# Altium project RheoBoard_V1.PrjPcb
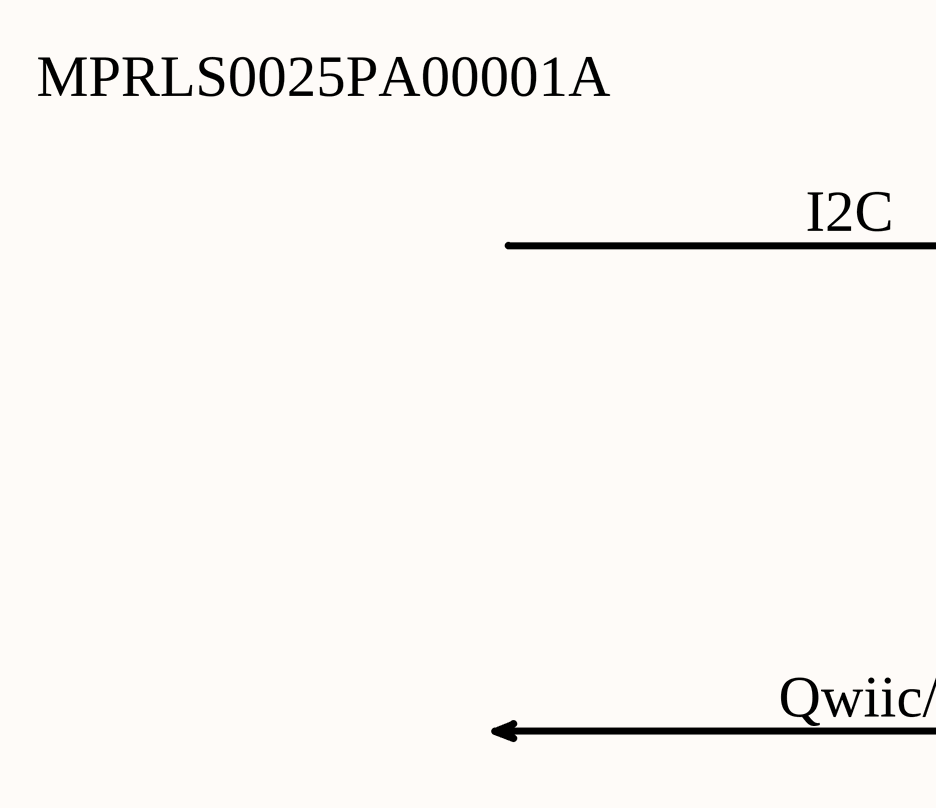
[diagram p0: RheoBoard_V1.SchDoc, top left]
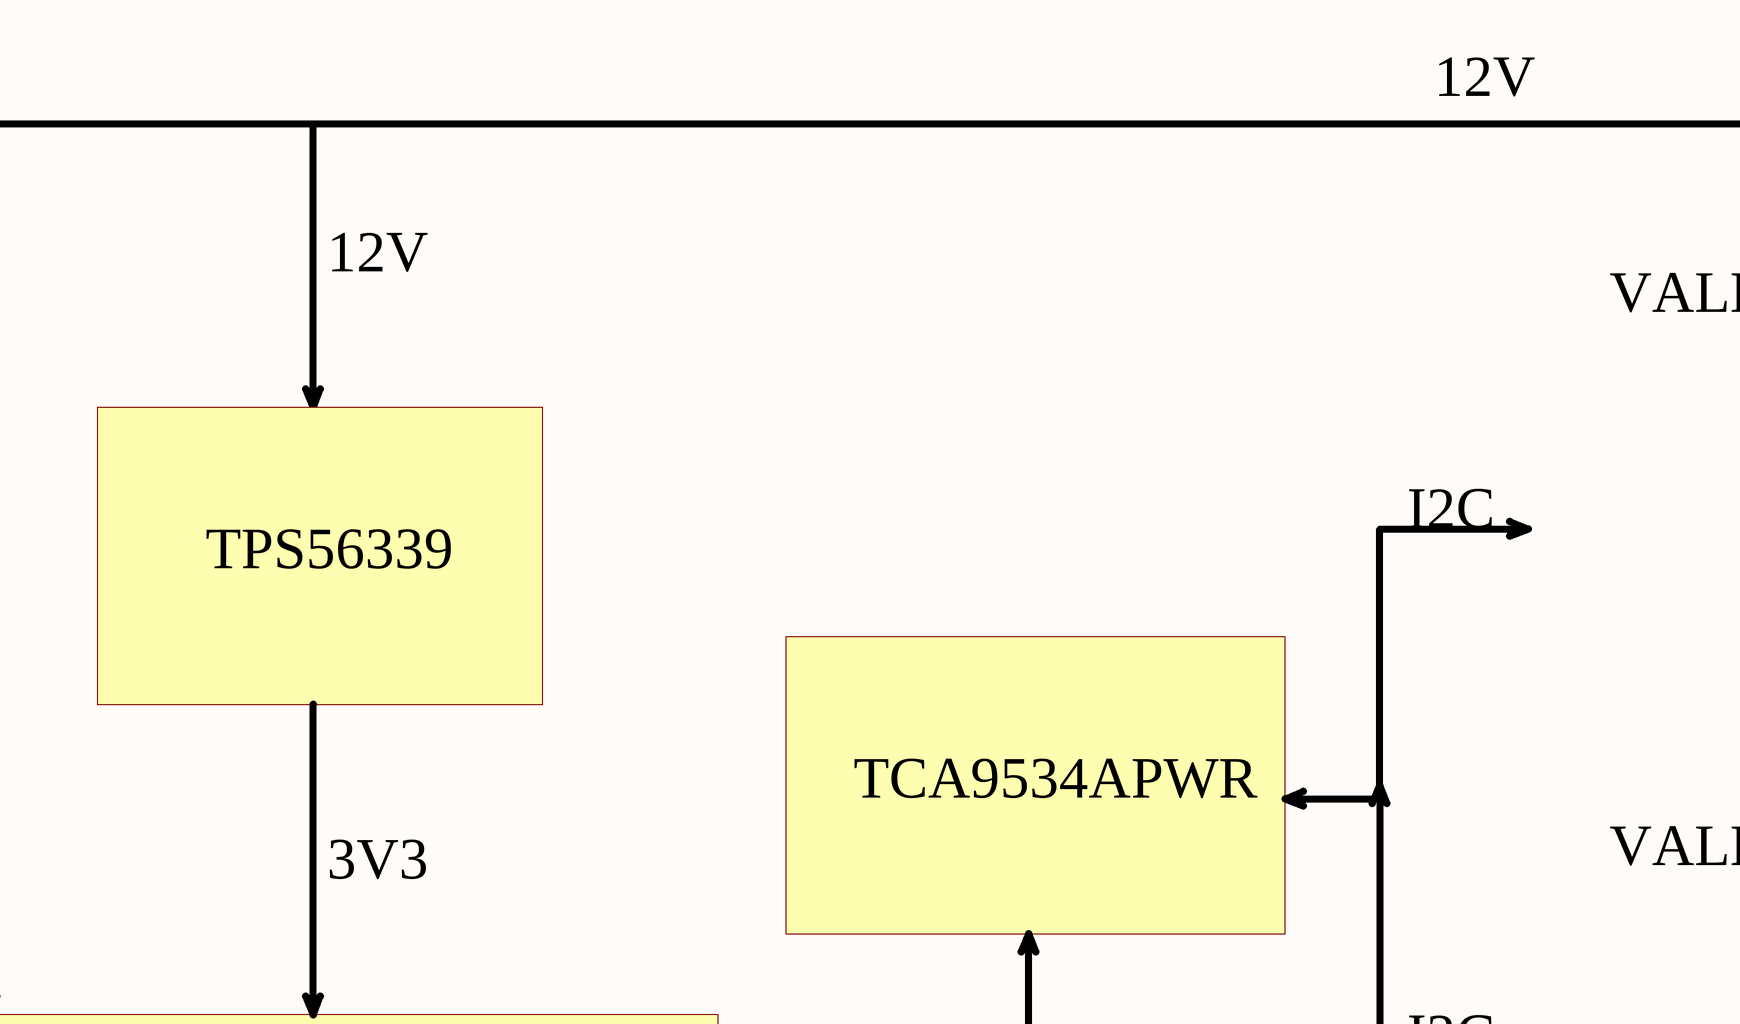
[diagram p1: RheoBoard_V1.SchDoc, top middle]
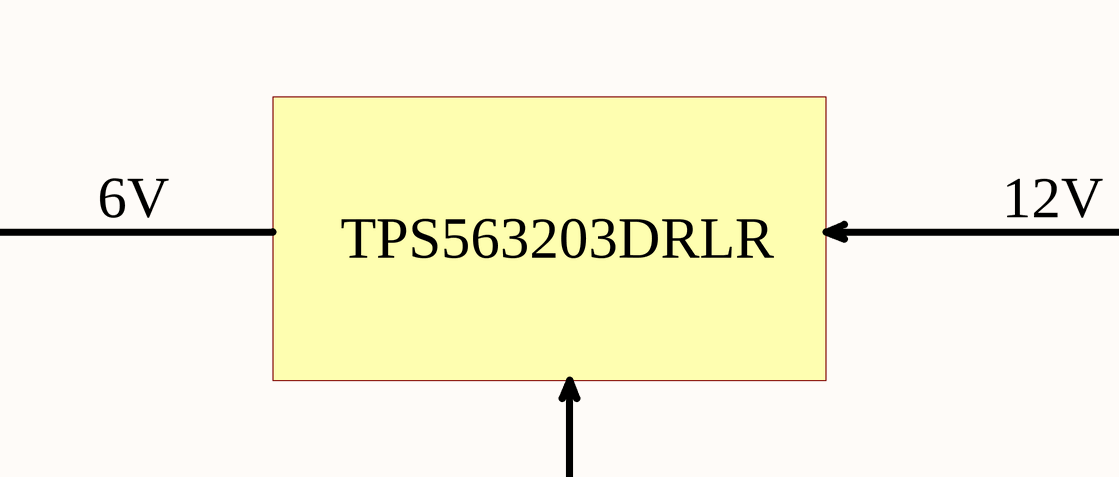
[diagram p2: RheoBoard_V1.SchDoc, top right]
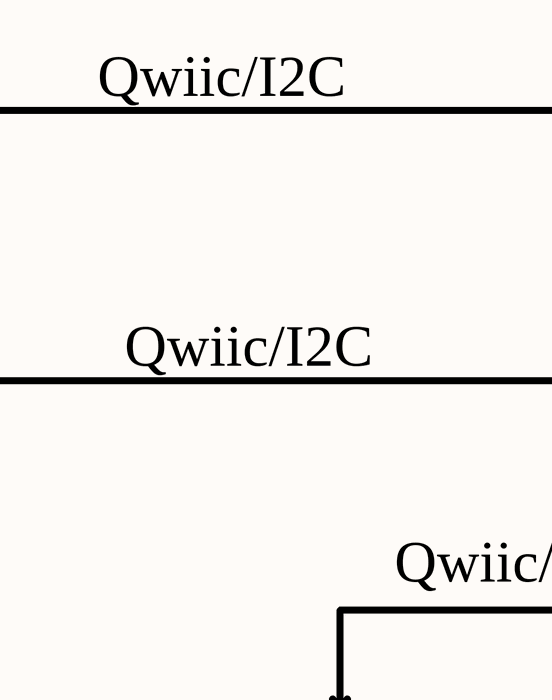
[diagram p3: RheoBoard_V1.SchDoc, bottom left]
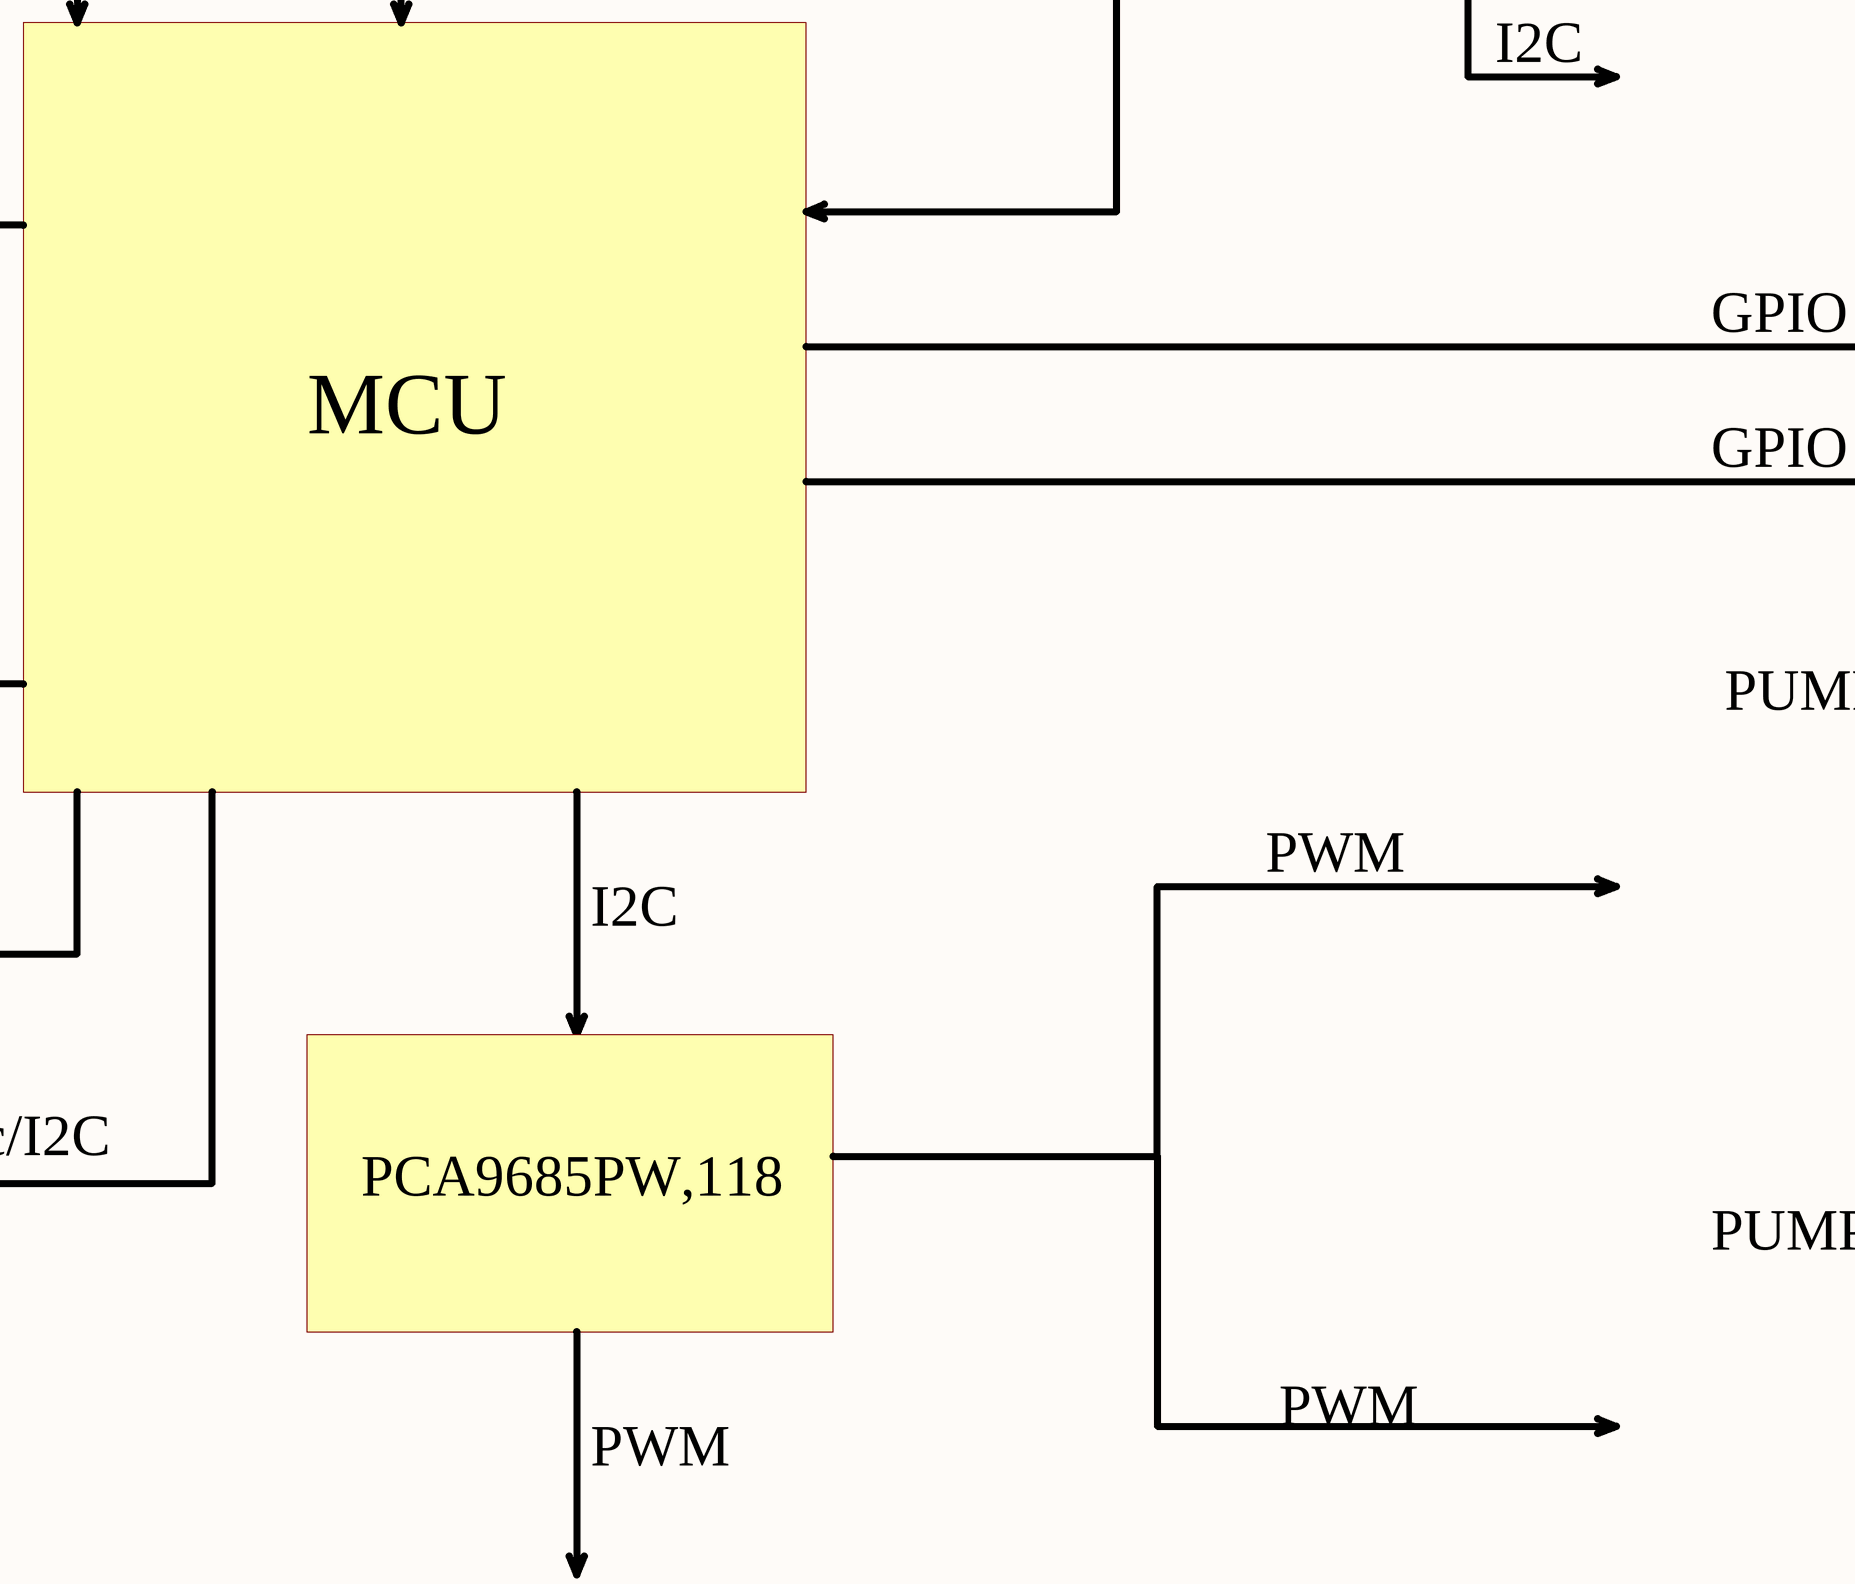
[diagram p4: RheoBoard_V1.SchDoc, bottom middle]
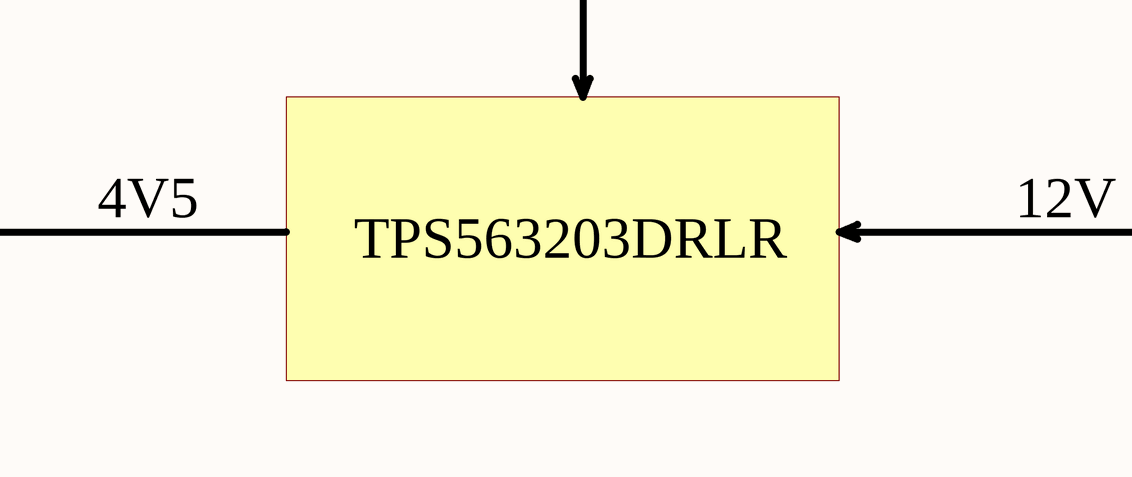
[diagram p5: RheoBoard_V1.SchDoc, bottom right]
3 sheets, 132 parts. Net scope: flat (ports and power ports of the same name join across sheets).
Board file: RheoBoard_V1.PcbDoc
Sheets:
  RheoBoard_V1.SchDoc
  MAIN.SchDoc
  POWER.SchDoc

## Sheet RheoBoard_V1.SchDoc
size A0; SheetNumber: 1; SheetTotal: 3

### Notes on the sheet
- 12V
- VALE1
- I2C
- MPRLS0025PA00001A
- TPS56339
- TCA9534APWR
- 6V
- 3V3
- VALE2
- TPS563203DRLR
- Qwiic/I2C
- GPIO
- MCU
- PUMP1
- PWM
- 4V5
- PCA9685PW,118
- PUMP2

## Sheet MAIN.SchDoc
size A1; SheetNumber: 2; SheetTotal: 3
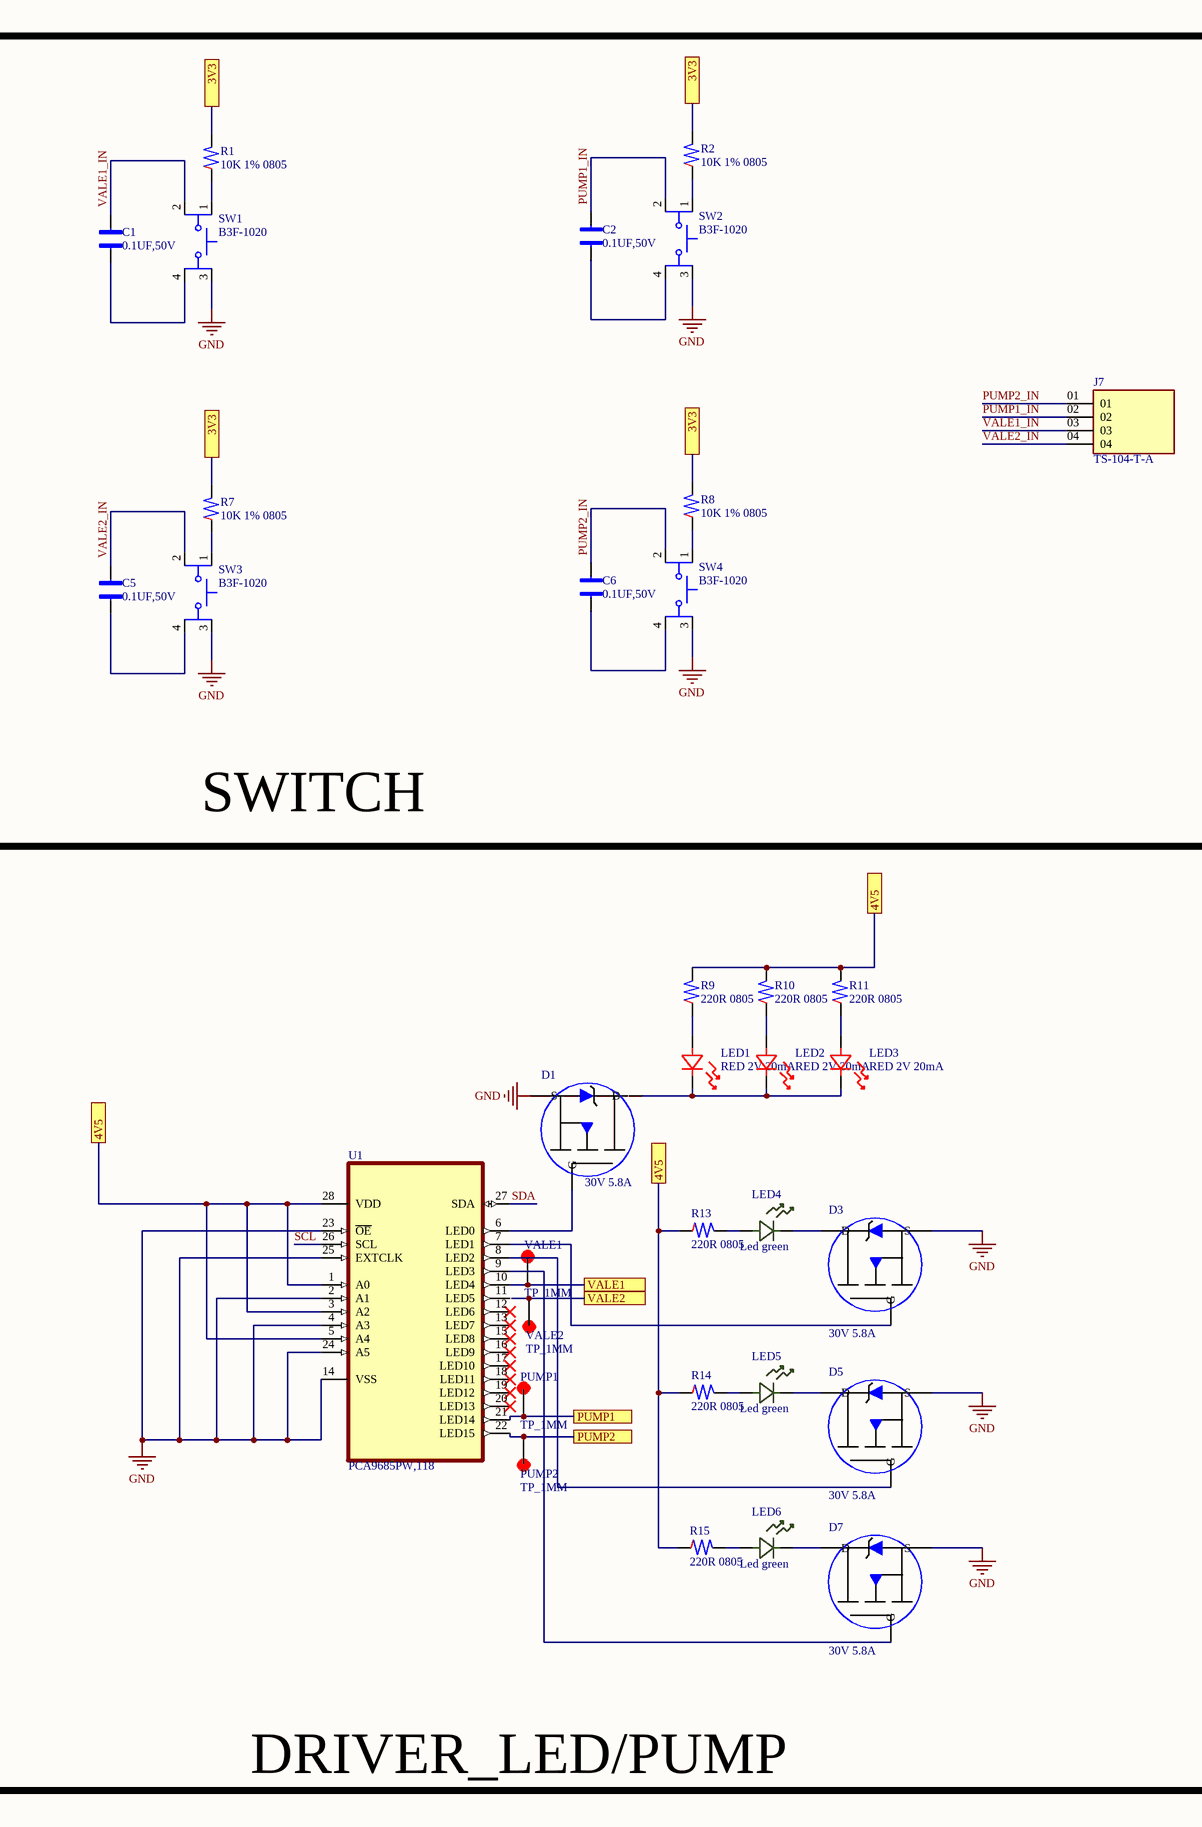
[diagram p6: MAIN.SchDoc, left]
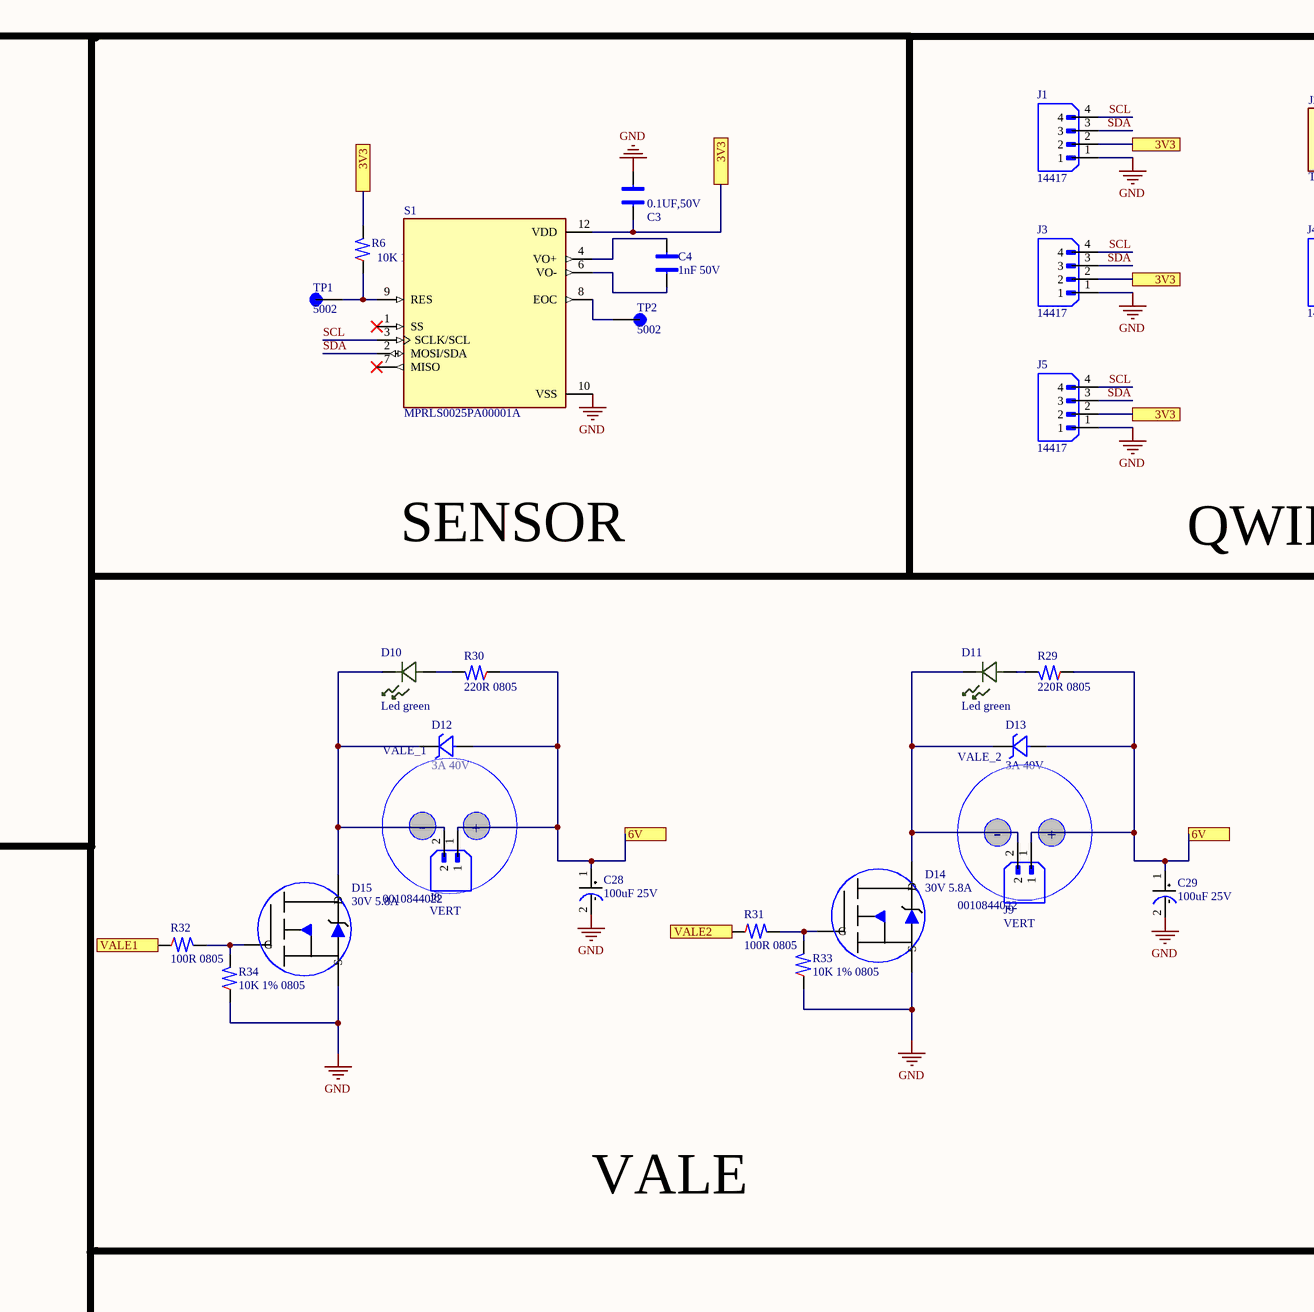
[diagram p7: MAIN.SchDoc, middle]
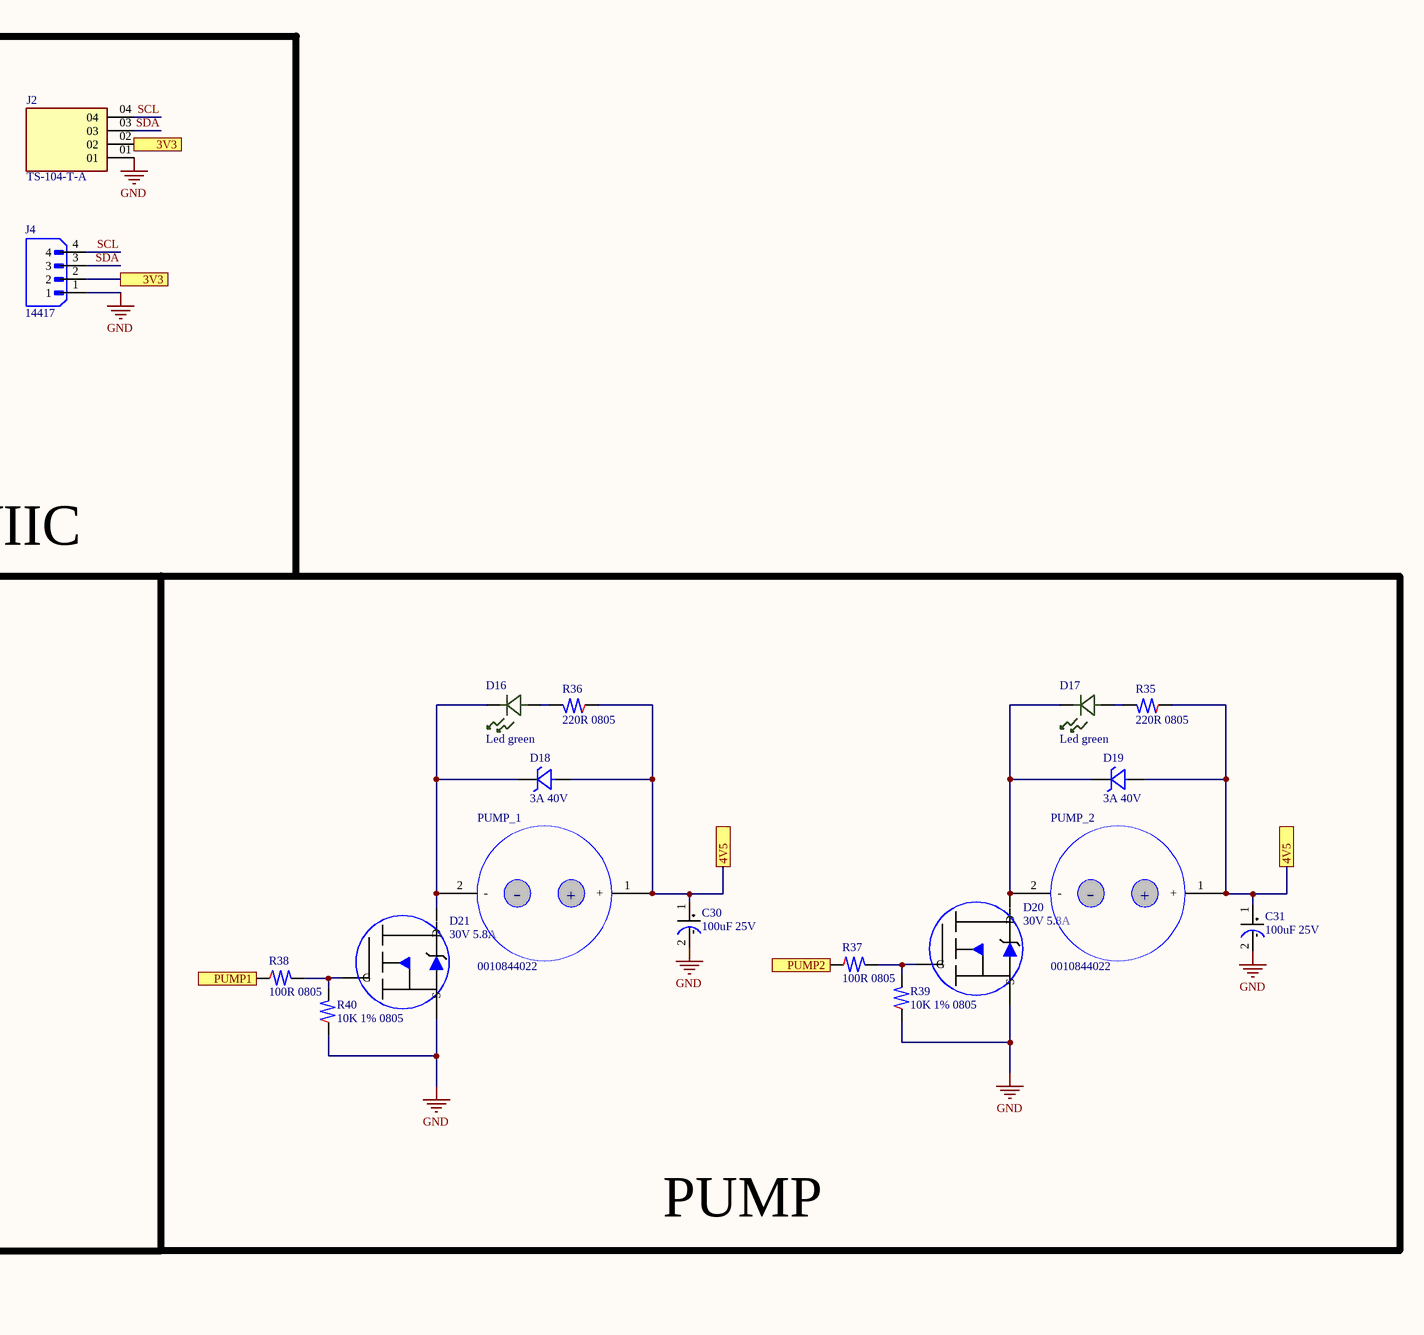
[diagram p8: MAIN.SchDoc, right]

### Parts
C1  0.1UF,50V  [CAP_CER_0805]
C2  0.1UF,50V  [CAP_CER_0805]
C3  0.1UF,50V  [CAP_CER_0805]
C4  1nF 50V  [CAP_CER_0805]
C5  0.1UF,50V  [CAP_CER_0805]
C6  0.1UF,50V  [CAP_CER_0805]
C28  100uF 25V  [CAP_ALUM_SMD_D10_H12.4]
C29  100uF 25V  [CAP_ALUM_SMD_D10_H12.4]
C30  100uF 25V  [CAP_ALUM_SMD_D10_H12.4]
C31  100uF 25V  [CAP_ALUM_SMD_D10_H12.4]
D1  30V 5.8A  [SOT-23-3]
D3  30V 5.8A  [SOT-23-3]
D5  30V 5.8A  [SOT-23-3]
D7  30V 5.8A  [SOT-23-3]
D10  Led green  [LED_LS R976_AOS]
D11  Led green  [LED_LS R976_AOS]
D12  3A 40V  [DO214AA]
D13  3A 40V  [DO214AA]
D14  30V 5.8A  [SOT-23-3]
D15  30V 5.8A  [SOT-23-3]
D16  Led green  [LED_LS R976_AOS]
D17  Led green  [LED_LS R976_AOS]
D18  3A 40V  [DO214AA]
D19  3A 40V  [DO214AA]
D20  30V 5.8A  [SOT-23-3]
D21  30V 5.8A  [SOT-23-3]
J1  14417  [SPARKFUN_PRT-14417]
J2  TS-104-T-A  [HDR_THT_1x04_P2.54]
J3  14417  [SPARKFUN_PRT-14417]
J4  14417  [SPARKFUN_PRT-14417]
J5  14417  [SPARKFUN_PRT-14417]
J7  TS-104-T-A  [HDR_THT_1x04_P2.54]
J8  VERT  [CONN_SMD_TOP_P2.50]
J9  VERT  [CONN_SMD_TOP_P2.50]
LED1  RED 2V 20mA  [LED_LS R976_AOS]
LED2  RED 2V 20mA  [LED_LS R976_AOS]
LED3  RED 2V 20mA  [LED_LS R976_AOS]
LED4  Led green  [LED_LS R976_AOS]
LED5  Led green  [LED_LS R976_AOS]
LED6  Led green  [LED_LS R976_AOS]
PUMP1  TP_1MM  [TP_1mm]
PUMP2  TP_1MM  [TP_1mm]
PUMP_1  0010844022  [PUMP_LPM - ZR370-02PM]
PUMP_2  0010844022  [PUMP_LPM - ZR370-02PM]
R1  10K 1% 0805  [RES_0805]
R2  10K 1% 0805  [RES_0805]
R6  10K 1% 0805  [RES_0805]
R7  10K 1% 0805  [RES_0805]
R8  10K 1% 0805  [RES_0805]
R9  220R 0805  [RES_0805]
R10  220R 0805  [RES_0805]
R11  220R 0805  [RES_0805]
R13  220R 0805  [RES_0805]
R14  220R 0805  [RES_0805]
R15  220R 0805  [RES_0805]
R29  220R 0805  [RES_0805]
R30  220R 0805  [RES_0805]
R31  100R 0805  [RES_0805]
R32  100R 0805  [RES_0805]
R33  10K 1% 0805  [RES_0805]
R34  10K 1% 0805  [RES_0805]
R35  220R 0805  [RES_0805]
R36  220R 0805  [RES_0805]
R37  100R 0805  [RES_0805]
R38  100R 0805  [RES_0805]
R39  10K 1% 0805  [RES_0805]
R40  10K 1% 0805  [RES_0805]
S1  MPRLS0025PA00001A  [XDCR_MPRLS0025PA00001A]
SW1  B3F-1020  [SW_B3F-1000_OMR]
SW2  B3F-1020  [SW_B3F-1000_OMR]
SW3  B3F-1020  [SW_B3F-1000_OMR]
SW4  B3F-1020  [SW_B3F-1000_OMR]
TP1  5002  [KEYSTONE_5002]
TP2  5002  [KEYSTONE_5002]
U1  PCA9685PW,118  [TSSOP-28]
VALE1  TP_1MM  [TP_1mm]
VALE2  TP_1MM  [TP_1mm]
VALE_1  0010844022  [VALE_FA0520E]
VALE_2  0010844022  [VALE_FA0520E]

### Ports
3V3, 4V5, 6V, PUMP1, PUMP2, VALE1, VALE2

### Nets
GND: C3.2 C28.2 C29.2 C30.2 C31.2 D1.2(S) D3.2(S) D5.2(S) D7.2(S) D14.2(S) D15.2(S) D20.2(S) D21.2(S) J1.1 J2.01 J3.1 J4.1 J5.1 R33.1 R34.1 R39.1 R40.1 S1.10(VSS) SW1.3 SW2.3 SW3.3 SW4.3 U1.2(A1) U1.4(A3) U1.14(VSS) U1.23(~{OE}) U1.24(A5) U1.25(EXTCLK)
PUMP1_IN: C2.2 J7.02 SW2.2
PUMP2_IN: C6.2 J7.01 SW4.2
SCL: J1.4 J2.04 J3.4 J4.4 J5.4 S1.3(SCLK/SCL) U1.26(SCL)
SDA: J1.3 J2.03 J3.3 J4.3 J5.3 S1.2(MOSI/SDA) U1.27(SDA)
VALE1_IN: C1.2 J7.03 SW1.2
VALE2_IN: C5.2 J7.04 SW3.2
Net3V3_1: C3.1 J1.2 J2.02 J3.2 J4.2 J5.2 R1.2 R2.2 R6.2 R7.2 R8.2 S1.12(VDD) ; port 3V3
Net4V5_1: C30.1 C31.1 D18.2(ANODE) D19.2(ANODE) PUMP_1.1(+) PUMP_2.1(+) R9.2 R10.2 R11.2 R13.1 R14.1 R15.1 R35.1 R36.1 U1.1(A0) U1.3(A2) U1.5(A4) U1.28(VDD) ; port 4V5
NetC1_1: C1.1 SW1.4
NetC2_1: C2.1 SW2.4
NetC4_1: C4.1 S1.6(VO-)
NetC4_2: C4.2 S1.4(VO+)
NetC5_1: C5.1 SW3.4
NetC6_1: C6.1 SW4.4
NetC14_2: C28.1 C29.1 D12.2(ANODE) D13.2(ANODE) J8.1 J9.1 R29.1 R30.1 ; port 6V
NetD1_1: D1.1(G) U1.6(LED0)
NetD1_3: D1.3(D) LED1.1 LED2.1 LED3.1
NetD3_1: D3.1(G) U1.7(LED1)
NetD3_3: D3.3(D) LED4.1
NetD5_1: D5.1(G) U1.8(LED2)
NetD5_3: D5.3(D) LED5.1
NetD7_1: D7.1(G) U1.9(LED3)
NetD7_3: D7.3(D) LED6.1
NetD10_1: D10.1 D12.1(CATHODE) D15.3(D) J8.2
NetD10_2: D10.2 R30.2
NetD11_1: D11.1 D13.1(CATHODE) D14.3(D) J9.2
NetD11_2: D11.2 R29.2
NetD14_1: D14.1(G) R31.2 R33.2
NetD15_1: D15.1(G) R32.2 R34.2
NetD16_1: D16.1 D18.1(CATHODE) D21.3(D) PUMP_1.2(-)
NetD16_2: D16.2 R36.2
NetD17_1: D17.1 D19.1(CATHODE) D20.3(D) PUMP_2.2(-)
NetD17_2: D17.2 R35.2
NetD20_1: D20.1(G) R37.2 R39.2
NetD21_1: D21.1(G) R38.2 R40.2
NetLED1_2: LED1.2 R9.1
NetLED2_2: LED2.2 R10.1
NetLED3_2: LED3.2 R11.1
NetLED4_2: LED4.2 R13.2
NetLED5_2: LED5.2 R14.2
NetLED6_2: LED6.2 R15.2
NetPUMP1_1: PUMP1.1 R38.1 U1.21(LED14) ; port PUMP1
NetPUMP2_1: PUMP2.1 R37.1 U1.22(LED15) ; port PUMP2
NetR1_1: R1.1 SW1.1
NetR2_1: R2.1 SW2.1
NetR6_1: R6.1 S1.9(RES) TP1.TP
NetR7_1: R7.1 SW3.1
NetR8_1: R8.1 SW4.1
NetR31_1: R31.1 VALE2.1 ; port VALE2
NetR32_1: R32.1 U1.10(LED4) VALE1.1 ; port VALE1
NetS1_8: S1.8(EOC) TP2.TP

Not connected (* = marked no-connect by the designer): S1 1(SS)* 7(MISO)*; U1 11(LED5) 12(LED6)* 13(LED7)* 15(LED8)* 16(LED9)* 17(LED10)* 18(LED11)* 19(LED12)* 20(LED13)*

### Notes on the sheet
- SENSOR
- QWIIC
- SWITCH
- VALE
- PUMP
- DRIVER_LED/PUMP

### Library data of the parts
C1-C3 C5 C6 = CAP_CER, 0805, X7R, 0.1UF, 5%, 50V: Ceramic Capacitor, Multilayer, Ceramic, 50V, 10% +Tol, 10% -Tol, X7R, 15% TC, 0.1uF, Surface Mount, 0805; Manufacturer: Nextgen; Manufacturer Part Number: 0805B104K500BD; Capacitance: 100nF; LIB MADE BY: MR HOANG
C4 = CAP_CER 0805 1NF 50V ULTRA STABL: Cap Ceramic 0.001uF 50V X8R 10% Pad SMD 0805 150C T/R Automotive AEC-Q200; Manufacturer: Yageo Group; Manufacturer Part Number: C0805C102K5HACAUTO; Temperature Coefficient: 30ppm/°C; LIB MADE BY: MR HOANG
C28-C31 = CAP ALUM POLY 100UF 20% 25V SMD: WCAP-PSLC Aluminum Polymer Capacitors; Manufacturer: Wurth Elektronik; Manufacturer Part Number: 875075561005; Manufacturer Lifecycle Status: ACTIVE; Capacitance: 100µF; ESR (Equivalent Series Resistance): 15mΩ; Leakage Current: 500µA; Life (Hours): 2000hours; Pitch: 10.3mm; Polarity: Polar; Ripple Current: 4.8A; Tolerance: 20%; YEOL: 1 = Estimated lifetime > 10 years; LIB MADE BY: MR HOANG
D1 D3 D5 D7 D14 D15 D20 D21 = MOSFET N-CH 30V 5.8A SOT23-3: Trans MOSFET N-CH 30V 5.7A 3-Pin SOT-23; Manufacturer: Alpha & Omega Semiconductor; Manufacturer Part Number: AO3400A; Drain to Source Resistance: 26.5mΩ; Gate to Source Voltage (Vgs): 12V; Input Capacitance: 630pF; Max Junction Temperature (Tj): 150°C; Max Power Dissipation: 1.4W; Number of Channels: 1; Threshold Voltage: 650mV; Turn-Off Delay Time: 25ns; Turn-On Delay Time: 3ns; LIB MADE BY: MR HOANG
D10 D11 D16 D17 LED4-LED6 = LED GREEN CLEAR CHIP SMD: Single-color LEDs; LITEON; LTST-C190GKT; Green; 130 °; 2.1 V; 0603; Manufacturer: Diodes Inc.; Current: 1A; Dominant Wavelength: 569nm; Forward Current: 30mA; Forward Voltage: 2.6V; Lens Color: Clear, Colorless; Lens Style: Clear; Luminous Intensity: 1.8mcd; Number of Circuits: 1; Peak Wavelength: 565nm; Power Dissipation: 100mW; Reverse Voltage: 5V; Shape: Rectangular; Test Current: 10mA; Viewing Angle: 130°; Voltage: 2V; LIB MADE BY: MR HOANG
D12 D13 D18 D19 = DIODE SCHOTTKY 40V 3A DO214AB: Rectifier Diode, Schottky, 1 Phase, 1 Element, 3A, 40V V(RRM), Silicon, DO-214AB; Manufacturer: onsemi; Manufacturer Part Number: SS34; Manufacturer Lifecycle Status: ACTIVE; Element Configuration: Single; Forward Voltage: 500mV; Max Forward Surge Current (Ifsm): 100A; Max Junction Temperature (Tj): 150°C; Max Power Dissipation: 2.27W; Max Reverse Leakage Current: 500µA; Number of Elements: 1; Peak Reverse Current: 20mA; Polarity: Standard; LIB MADE BY: MR HOANG
J1 J3-J5 = QWIIC CONNECTOR SMD 4-PIN: Manufacturer: SparkFun; LIB MADE BY: MR HOANG
J2 J7 = CONN HEADER VERT 4POS 2.54MM: Samtec 2.54mmpitch4pSingle row pin header, TSseries, right angle, Through hole mounting; Manufacturer Lifecycle Status: PRODUCTION; Gender: Male; Number of Contacts: 4; Pitch: 2.54mm; LIB MADE BY: MR HOANG
J8 J9 = CONN HEADER VERT 2POS 2.5MM: Board Connector, 2 Contact(s), 1 Row(s), Male, Straight, Solder Terminal; Manufacturer: JST; Manufacturer Part Number: B2B-XH-A; Contact Resistance: 20mΩ; Current Rating: 3A; Insulation Resistance: 1GΩ; LIB MADE BY: MR HOANG
LED1-LED3 = LED RED DIFFUSED 0805 SMD: Red 633nm LED Indication - Discrete 2V 0805 (2012 Metric); Manufacturer: Osram; Manufacturer Part Number: LS R976-NR-1-0-20-R18; LIB MADE BY: MR HOANG
PUMP_1 PUMP_2 = Air Pump and Vacuum DC Motor - 4.5 V and 2.5 LPM - ZR370-02PM: Connector Header 2 Position 6.35mm Solder Straight Thru-Hole 2 Terminal 1 Port MLX-Series; Manufacturer: Molex; Manufacturer Lifecycle Status: ACTIVE; Connector Type: Power; Contact Resistance: 3.5mΩ; Current Rating: 13.5A; Dielectric Material: Polyester; Gender: Female; Glow Wire Compliant: Non-compliant; Insulation Resistance: 1GΩ; Number of Circuits: 2; Operating Force: 6.672N; Plating: Tin; Plating Thickness: 3.5052µm; Ratings: CSA; Voltage Rating: 600V; LIB MADE BY: MR HOANG
R1 R2 R6-R8 R33 R34 R39 R40 = RES_SMD 10K 1% 1/4W 0805: Res Thick Film 0805 10K Ohm 1% 0.125W(1/8W) ±100ppm/C Pad SMD Automotive T/R; Manufacturer: Vishay; Manufacturer Part Number: CRCW080510K0FKEA; Manufacturer Package Identifier: CRCW0805-e3; Power Dissipation: 125mW; Power Rating: 120mW; Resistance: 10kΩ; Temperature Coefficient: 100ppm/°C; Voltage Rating: 150V; LIB MADE BY: MR HOANG
R9-R11 R13-R15 R29 R30 R35 R36 = RES_SMD 220 OHM 1% 1/8W 0805: Res Thick Film 0805 220 Ohm 1% 0.125W(1/8W) ±100ppm/C Pad SMD Automotive T/R; Manufacturer: TE Connectivity; Manufacturer Part Number: CRGCQ0805F220R; Manufacturer Lifecycle Status: ACTIVE; Operating Supply Voltage: 150V; Power Rating: 125mW; Resistance: 220Ω; Temperature Coefficient: 100ppm/°C; LIB MADE BY: MR HOANG
R31 R32 R37 R38 = RES_SMD 100 OHM 1% 1/8W 0805: Resistor Thick Film 0805 100 Ohm 1% 1/8W 100ppm/C Molded SMD Punched Carrier T/R; Manufacturer: Panasonic; Manufacturer Part Number: ERJ6ENF1000V; Manufacturer Lifecycle Status: ACTIVE; Manufacturer Package Identifier: 0805 (2012 metric); Part Series: Precision Thick Film Chip Resistors; Max Power Dissipation: 125mW; Resistance: 100Ω; Temperature Coefficient: 100ppm/°C; Voltage Rating: 150V; LIB MADE BY: MR HOANG
S1 = SENSOR 25PSIA 0.1" 24BIT: Board Mount Pressure Sensor -0.3V to 3.9V 0psi to 25psi Absolute 12-Pin T/R; Manufacturer: Honeywell; Accuracy: 0.25%; Current Rating: 1.7mA; Max Supply Voltage: 3.6V; Min Supply Voltage: 1.8V; Number of Bits: 14; Operating Supply Current: 33.8µA; Port Style: Barbless; LIB MADE BY: MR HOANG
SW1-SW4 = SWITCH TACTILE SPST-NO 0.05A 24V: Switch Tactile N.O. SPST Flat Round Button PC Pins 0.05A 24VDC 0.98N Thru-Hole Bag; Manufacturer: Omron; Actuator Length: 900µm; Contact Current Rating: 50mA; Contact Resistance: 100mΩ; Electrical Life: 1Mcycles; Illumination Type: Illuminated, Non-Illuminated; Max Voltage Rating (DC): 24V; Number of Poles: 1; Operating Force: 1.27N; Switch Function: Off-Mom; Switch Travel: 250µm; LIB MADE BY: MR HOANG
TP1 TP2 = PC TEST POINT MINIATURE WHITE: Test Point, Mini, Thm, Pc, .300 L, .100 Od, Heat Resistant Nylon 46, White; Manufacturer: Keystone; Body Material: Bronze, PBT; Hole Diameter: 1.6mm; Inside Diameter: 1.27mm; Insulation: Insulated; Number of Ports: 1; Outside Diameter: 2.54mm; Plating: Silver; LIB MADE BY: MR HOANG
U1 = IC LED DRVR LIN PWM 25MA 28TSSOP: PCA9685 Series 5.5V 25 mA 1 MHz 12-bit PWM Fm+I2C-Bus LED Controller - TSSOP-28; Manufacturer: NXP Semiconductors; Frequency: 25MHz; High Level Output Current: 10mA; Low Level Output Current: 400A; Max Power Dissipation: 400mW; Min Supply Voltage: 2.3V; Nominal Supply Current: 6mA; Nominal Supply Voltage (DC): 3V; Number of Characters: 16; Number of Circuits: 1; Output Current: 25mA; Output Voltage: 5V; Power Dissipation: 400W; LIB MADE BY: MR HOANG
VALE_1 VALE_2 = 6V Air Valve with 2-pin JST XH Connector - FA0520E: Connector Header 2 Position 6.35mm Solder Straight Thru-Hole 2 Terminal 1 Port MLX-Series; Manufacturer: Molex; Manufacturer Lifecycle Status: ACTIVE; Connector Type: Power; Contact Resistance: 3.5mΩ; Current Rating: 13.5A; Dielectric Material: Polyester; Gender: Female; Glow Wire Compliant: Non-compliant; Insulation Resistance: 1GΩ; Number of Circuits: 2; Operating Force: 6.672N; Plating: Tin; Plating Thickness: 3.5052µm; Ratings: CSA; Voltage Rating: 600V; LIB MADE BY: MR HOANG

## Sheet POWER.SchDoc
size A2; SheetNumber: 3; SheetTotal: 3
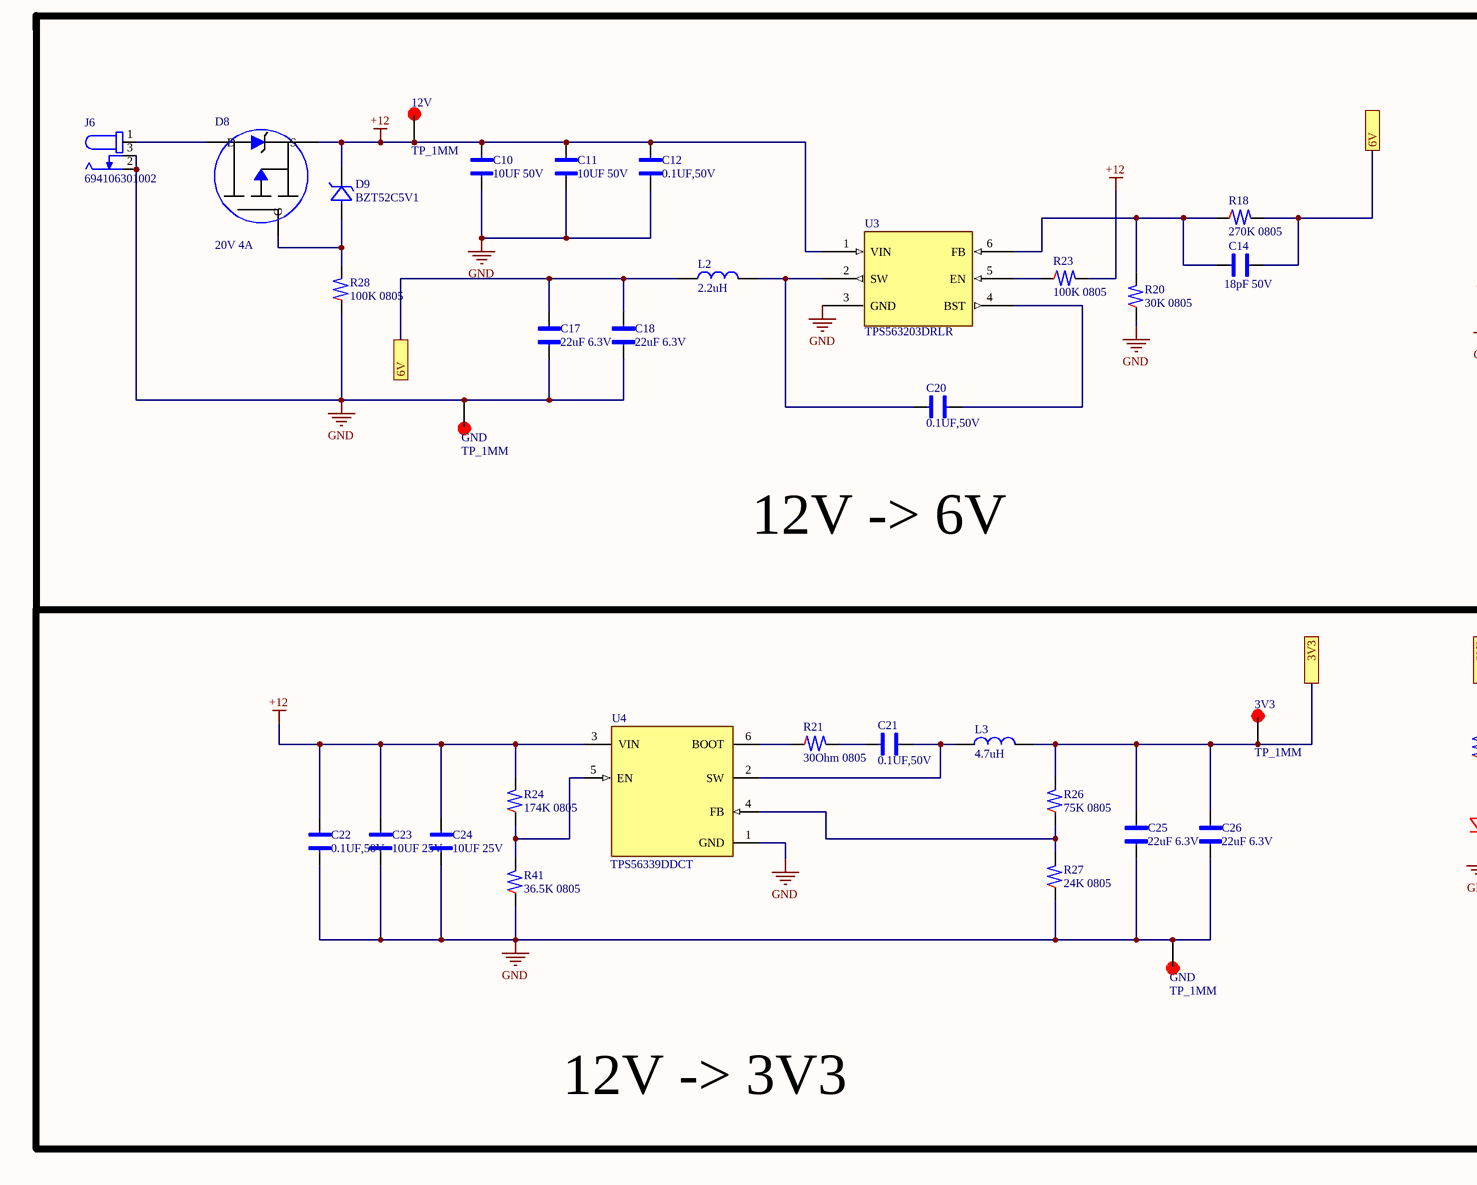
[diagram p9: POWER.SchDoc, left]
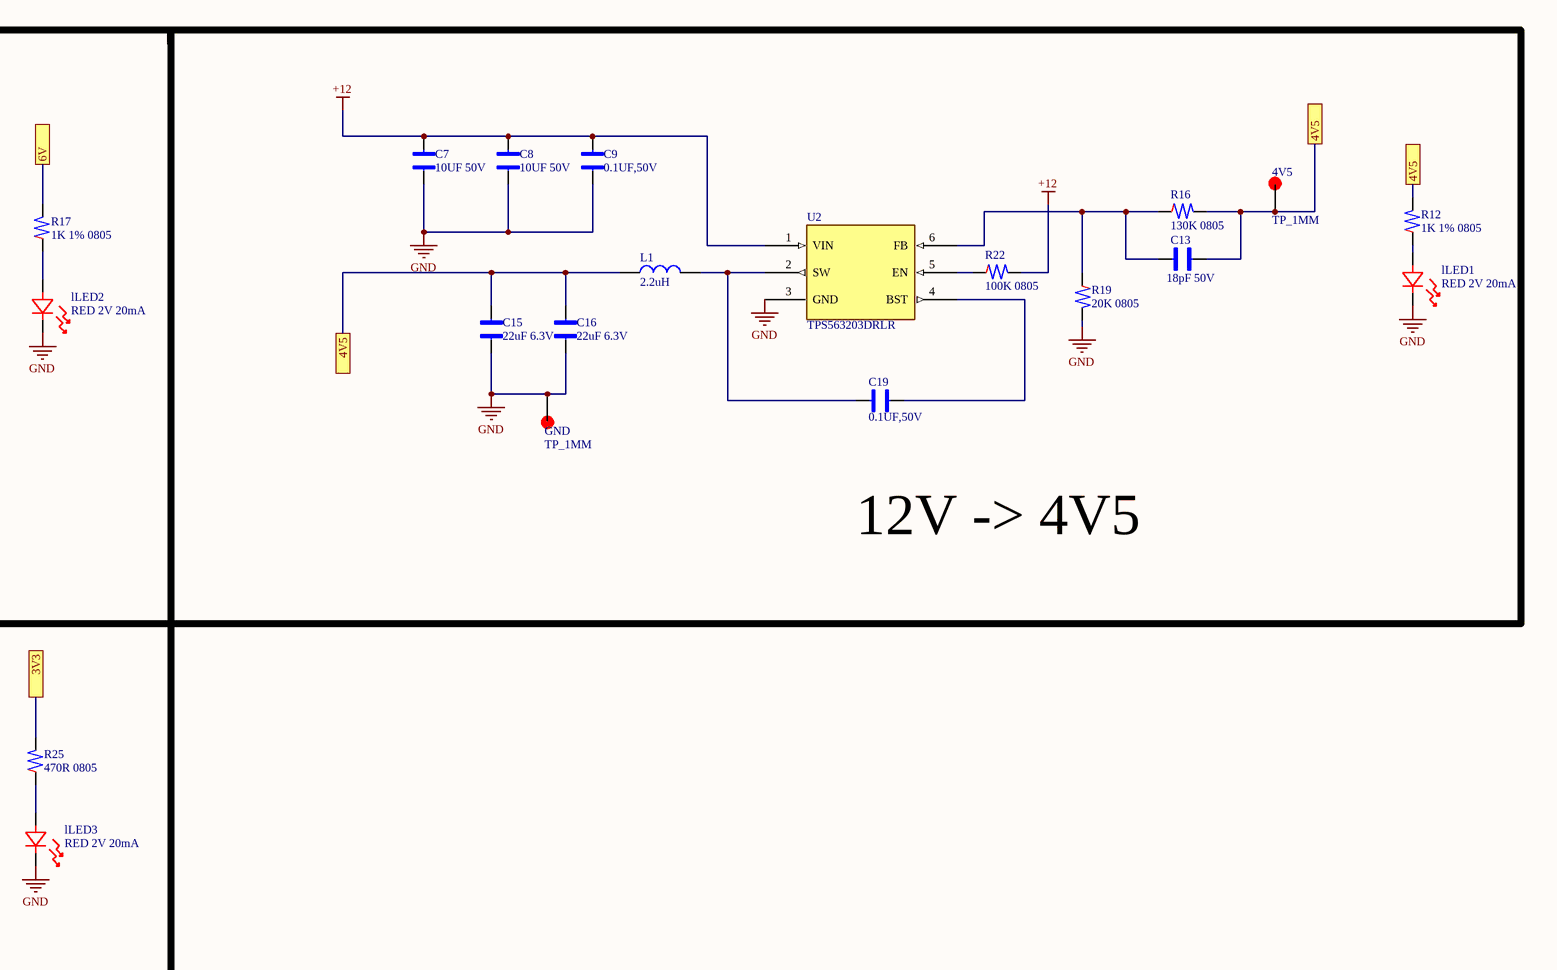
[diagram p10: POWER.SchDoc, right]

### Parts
(Parts that share a designator on the sheet are numbered #1, #2 ... from top to bottom, then left to right.)
3V3  TP_1MM  [TP_1mm]
4V5  TP_1MM  [TP_1mm]
12V  TP_1MM  [TP_1mm]
C7  10UF 50V  [CAP_CER_0805]
C8  10UF 50V  [CAP_CER_0805]
C9  0.1UF,50V  [CAP_CER_0805]
C10  10UF 50V  [CAP_CER_0805]
C11  10UF 50V  [CAP_CER_0805]
C12  0.1UF,50V  [CAP_CER_0805]
C13  18pF 50V  [CAP_CER_0805]
C14  18pF 50V  [CAP_CER_0805]
C15  22uF 6.3V  [CAP_CER_0603]
C16  22uF 6.3V  [CAP_CER_0603]
C17  22uF 6.3V  [CAP_CER_0603]
C18  22uF 6.3V  [CAP_CER_0603]
C19  0.1UF,50V  [CAP_CER_0805]
C20  0.1UF,50V  [CAP_CER_0805]
C21  0.1UF,50V  [CAP_CER_0805]
C22  0.1UF,50V  [CAP_CER_0805]
C23  10UF 25V  [CAP_CER_0805]
C24  10UF 25V  [CAP_CER_0805]
C25  22uF 6.3V  [CAP_CER_0603]
C26  22uF 6.3V  [CAP_CER_0603]
D8  20V 4A  [SOT-23-3]
D9  BZT52C5V1  [SOD-123]
GND#1  TP_1MM  [TP_1mm]
GND#2  TP_1MM  [TP_1mm]
GND#3  TP_1MM  [TP_1mm]
J6  694106301002  [CONN PWR JACK 2.1X5.5MM SOLDER]
L1  2.2uH  [IND_12.5x12.5_H8.5]
L2  2.2uH  [IND_12.5x12.5_H8.5]
L3  4.7uH  [IND_6.8X6.5_H2.8]
lLED1  RED 2V 20mA  [LED_LS R976_AOS]
lLED2  RED 2V 20mA  [LED_LS R976_AOS]
lLED3  RED 2V 20mA  [LED_LS R976_AOS]
R12  1K 1% 0805  [RES_0805]
R16  130K 0805  [RES_0805]
R17  1K 1% 0805  [RES_0805]
R18  270K 0805  [RES_0805]
R19  20K 0805  [RES_0805]
R20  30K 0805  [RES_0805]
R21  30Ohm 0805  [RES_0805]
R22  100K 0805  [RES_0805]
R23  100K 0805  [RES_0805]
R24  174K 0805  [RES_0805]
R25  470R 0805  [RES_0805]
R26  75K 0805  [RES_0805]
R27  24K 0805  [RES_0805]
R28  100K 0805  [RES_0805]
R41  36.5K 0805  [RES_0805]
U2  TPS563203DRLR  [SOT-563]
U3  TPS563203DRLR  [SOT-563]
U4  TPS56339DDCT  [SOT-23-6]

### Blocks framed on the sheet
12V -> 3V3: 3V3 C21-C26 GND#3 L3 lLED3 R21 R24-R27 R41 U4

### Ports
3V3, 4V5, 6V

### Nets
+12: 12V.1 C7.2 C8.2 C9.2 C10.2 C11.2 C12.2 C22.2 C23.2 C24.2 D8.2(S) D9.1(CATHODE) R22.2 R23.2 R24.2 U2.1(VIN) U3.1(VIN) U4.3(VIN)
GND: C7.1 C8.1 C9.1 C10.1 C11.1 C12.1 C15.1 C16.1 C17.1 C18.1 C22.1 C23.1 C24.1 C25.1 C26.1 GND#1.1 GND#2.1 GND#3.1 J6.2 J6.3 lLED1.1 lLED2.1 lLED3.1 R19.2 R20.1 R27.1 R28.1 R41.1 U2.3(GND) U3.3(GND) U4.1(GND)
Net3V3_1: 3V3.1 C25.2 C26.2 L3.2 R25.2 R26.2 ; port 3V3
Net4V5_1: 4V5.1 C13.2 C15.2 C16.2 L1.1 R12.2 R16.2 ; port 4V5
NetC13_1: C13.1 R16.1 R19.1 U2.6(FB)
NetC14_1: C14.1 R18.1 R20.2 U3.6(FB)
NetC14_2: C14.2 C17.2 C18.2 L2.1 R17.2 R18.2 ; port 6V
NetC19_1: C19.1 L1.2 U2.2(SW)
NetC19_2: C19.2 U2.4(BST)
NetC20_1: C20.1 L2.2 U3.2(SW)
NetC20_2: C20.2 U3.4(BST)
NetC21_1: C21.1 L3.1 U4.2(SW)
NetC21_2: C21.2 R21.2
NetD8_1: D8.1(G) D9.2(ANODE) R28.2
NetD8_3: D8.3(D) J6.1
NetlLED1_2: lLED1.2 R12.1
NetlLED2_2: lLED2.2 R17.1
NetlLED3_2: lLED3.2 R25.1
NetR21_1: R21.1 U4.6(BOOT)
NetR22_1: R22.1 U2.5(EN)
NetR23_1: R23.1 U3.5(EN)
NetR24_1: R24.1 R41.2 U4.5(EN)
NetR26_1: R26.1 R27.2 U4.4(FB)

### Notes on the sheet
- 12V -> 6V
- 12V -> 4V5

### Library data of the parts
C7 C8 C10 C11 = CAP_CER, 0805, X5R, 10UF, 10%, 50V: CAP_CER,0805,X5R,10UF,10%,50V; Manufacturer: Nextgen; Manufacturer Part Number: 0805W106K500CC; LIB MADE BY: MR HOANG
C9 C12 C19-C22 = CAP_CER, 0805, X7R, 0.1UF, 5%, 50V: as C1 on sheet MAIN
C13 C14 = CAP_CER, 18PF 50V X8R 0805: Multilayer Ceramic Capacitors MLCC - SMD/SMT 50V 18pF X8R 0805 5%; Manufacturer: Yageo Group; Manufacturer Part Number: C0805C180J5HACTU; Temperature Coefficient: 30ppm/°C; LIB MADE BY: MR HOANG
C15-C18 C25 C26 = CAP_CER 22UF 6.3V X6S 0603: 6.3V 22uF X6S ±20% 0603 Multilayer Ceramic Capacitors MLCC - SMD/SMT ROHS; Manufacturer: Murata; Manufacturer Part Number: GRM188C80J226ME15D; Manufacturer Lifecycle Status: IN PRODUCTION; Capacitance: 22µF; LIB MADE BY: MR HOANG
C23 C24 = CAP_CER, 0805, X5R, 10UF, 10%, 25V: Cap SMD, 0805, X5R, 10UF, 10%, 25V; Manufacturer: Nextgen; Manufacturer Part Number: 0805W106K250CC; LIB MADE BY: MR HOANG
D8 = MOSFET P-CH 20V 4A SOT23-3: P-ch Mosfet 20V 4A 39MΩ@4A, 4.5V 9.1NC@4.5V 294PF@10V SOT-23-3 SMD 2.9MM × 1.3MM × 1.03MM; Manufacturer: Diodes Inc.; Manufacturer Part Number: DMG3415U-7; Drain to Source Breakdown Voltage: -20V; Drain to Source Resistance: 42.5mΩ; Element Configuration: Single; Fall Time: 393ns; Gate to Source Voltage (Vgs): 8V; Input Capacitance: 294pF; Max Junction Temperature (Tj): 150°C; Max Power Dissipation: 900mW; Nominal Vgs: -550mV; Number of Channels: 1; Rds On Max: 39mΩ; Rise Time: 117ns; Turn-Off Delay Time: 795ns; Turn-On Delay Time: 71ns; LIB MADE BY: MR HOANG
D9 = DIODE ZENER 5.1V 500MW SOD123F: BZT52C5V1 Series 500 mW 5.1 V 10 mA Surface Mount Zener Diode - SOD-123; Manufacturer: Diodes Inc.; Manufacturer Part Number: BZT52C5V1-7-F; Current: 1A; Element Configuration: Single; Forward Current: 10mA; Forward Voltage: 900mV; Impedance: 60Ω; Max Junction Temperature (Tj): 150°C; Max Power Dissipation: 370mW; Max Reverse Leakage Current: 2µA; Number of Elements: 1; Output Current: 50mA; Polarity: Unidirectional; Power Rating: 500mW; Reference Voltage: 5.1V; Reverse Standoff Voltage: 2V; Test Current: 5mA; Tolerance: 6%; Voltage Tolerance: 5.88%; LIB MADE BY: MR HOANG
J6 = CONN PWR JACK 2.1X5.5MM SOLDER: DC Power Jack Connector WR-DC, Male, Right Angled, THT, 5 A, 24 V; Manufacturer: Wurth Elektronik; Manufacturer Lifecycle Status: ACTIVE; Current Rating: 5A; Insulation Resistance: 100MΩ; Number of Contacts: 3; Operating Supply Voltage: 24V; Shielding: Unshielded; YEOL: 1 = Estimated lifetime > 10 years; LIB MADE BY: MR HOANG
L1 L2 = FIXED IND 2.2UH 3A 45 MOHM SMD: Inductor Power Shielded Wirewound 2.2uH 20% 100KHz Ferrite 3.1A 0.045Ohm DCR 1515 T/R; Manufacturer: Vishay; Manufacturer Part Number: IFSC1515AHER2R2M01; Current Rating: 3A; DC Resistance (DCR): 45mΩ; Inductance: 2.2µH; Max Current Rating: 2.8A; Number of Circuits: 1; Resistance: 35mΩ; LIB MADE BY: MR HOANG
L3 = FIXED IND 4.7UH 6.3A 33 MOHM SMD: FIXED IND 4.7UH 6.3A 33MOHM SMD / 4.7 µH Shielded Molded Inductor 6.3 A 33mOhm Max Nonstandard; Manufacturer: Sumida; Manufacturer Part Number: 0630CDMCCDS-4R7MC; Core Material: Metal; DC Resistance (DCR): 33mΩ; Inductance: 4.7µH; Number of Circuits: 1; Saturation Current: 6.8A; Test Frequency: 100kHz; Tolerance: 20%
lLED1-lLED3 = LED RED DIFFUSED 0805 SMD: as LED1 on sheet MAIN
R12 R17 = RES_SMD 1K 1% 1/8W 0805: Yageo RC0805FR-071KL SMD Resistor 0603 1k Ohm ±1% Thick Film; Manufacturer: Yageo Group; Max Power Dissipation: 125mW; Resistance: 1kΩ; Temperature Coefficient: 100ppm/°C; Voltage Rating: 150V; LIBRARY MADE BY: Mr. HOANG
R16 = RES_SMD 130K OHM 1% 1/8W 0805: Res Thick Film 0805 130K Ohm 1% 0.125W(1/8W) ±100ppm/C Pad SMD T/R; Manufacturer: Yageo Group; Manufacturer Part Number: RC0805FR-07130KL; Max Power Dissipation: 125mW; Resistance: 130kΩ; Temperature Coefficient: 100ppm/°C; Voltage Rating: 150V; LIB MADE BY: MR HOANG
R18 = RES_SMD 270K OHM 5% 1/8W 0805: Res Thick Film 0805 270K Ohm 5% 0.125W(1/8W) ±100ppm/C Pad SMD T/R; Manufacturer: Yageo Group; Manufacturer Part Number: RC0805JR-07270KL; Manufacturer Package Identifier: 0805 (2012 metric); Max Power Dissipation: 125mW; Resistance: 270kΩ; Temperature Coefficient: 100ppm/°C; Voltage Rating: 150V; LIB MADE BY: MR HOANG
R19 = RES_SMD 20K OHM 1% 1/8W 0805: Res Thick Film 0805 20K Ohm 1% 1/8W ±100ppm/°C Molded SMD Punched Carrier T/R; Manufacturer: Panasonic; Manufacturer Part Number: ERJ6ENF2002V; Manufacturer Lifecycle Status: ACTIVE; Part Series: Precision Thick Film Chip Resistors; Max Power Dissipation: 125mW; Resistance: 20kΩ; Voltage Rating: 150V; LIB MADE BY: MR HOANG
R20 = RES_SMD 30K OHM 1% 1/8W 0805: Res Thick Film 0805 30K Ohm 1% 0.125W ±100ppm/°C Molded SMD Paper T/R; Manufacturer: Stackpole Electronics; Manufacturer Part Number: RMCF0805FT30K0; Manufacturer Package Identifier: 0805 (2012 metric); Max Power Dissipation: 125mW; Resistance: 30kΩ; Voltage Rating: 150V; LIB MADE BY: MR HOANG
R21 = RES_SMD 30 OHM 1% 1/8W 0805: Res Thick Film 0805 30 Ohm 1% 0.125W(1/8W) ±100ppm/C Pad SMD T/R; Manufacturer: Yageo Group; Manufacturer Part Number: RC0805FR-0730RL; Manufacturer Package Identifier: 0805 (2012 metric); Max Power Dissipation: 125mW; Resistance: 30Ω; Temperature Coefficient: 100ppm/°C; Voltage Rating: 150V; LIB MADE BY: MR HOANG
R22 R23 R28 = RES_SMD 100K 1% 1/8W 0805: 125mW Thick Film Resistors 150V ±100ppm/℃ ±1% 100kΩ 0805 Chip Resistor - Surface Mount ROHS; Manufacturer: Yageo Group; Manufacturer Part Number: RC0805FR-07100KL; Temperature Coefficient: 100ppm/°C; LIB MADE BY: MR HOANG
R24 = RES_SMD 174K OHM 1% 1/8W 0805: Res Thick Film 0805 174K Ohm 1% 0.125W(1/8W) ±100ppm/C Pad SMD T/R Automotive AEC-Q200; Manufacturer: Vishay; Manufacturer Part Number: CRCW0805174KFKEA; Manufacturer Package Identifier: CRCW0805-e3; Max Power Dissipation: 125mW; Resistance: 174kΩ; Temperature Coefficient: 100ppm/°C; Voltage Rating: 150V; LIB MADE BY: MR HOANG
R25 = RES_SMD 470 OHM 5% 1/8W 0805: Res Thick Film 0805 470 Ohm 5% 0.125W(1/8W) ±100ppm/C Pad SMD T/R Automotive AEC-Q200; Manufacturer: TE Connectivity; Manufacturer Part Number: CRGCQ0805J470R; Manufacturer Lifecycle Status: ACTIVE; Operating Supply Voltage: 150V; Power Rating: 125mW; Resistance: 470Ω; Temperature Coefficient: 100ppm/°C
R26 = RES_SMD 75K OHM 1% 1/8W 0805: Res Thick Film 0805 75K Ohm 1% 1/8W ±100ppm/°C Molded SMD SMD Paper Tape on Plastic Reel; Manufacturer: Bourns; Manufacturer Part Number: CR0805-FX-7502ELF; Power Rating: 125mW; Resistance: 75kΩ; Voltage Rating: 150V; LIB MADE BY: MR HOANG
R27 = RES_SMD 24K OHM 1% 1/8W 0805: Res Thick Film 0805 24K Ohm 1% 0.125W(1/8W) ±100ppm/C Pad SMD T/R; Manufacturer: Yageo Group; Manufacturer Part Number: RC0805FR-0724KL; Manufacturer Package Identifier: 0805 (2012 metric); Power Rating: 125mW; Resistance: 24kΩ; Temperature Coefficient: 100ppm/°C; Voltage Rating: 150V; LIB MADE BY: MR HOANG
R41 = RES_SMD 36.5K OHM 1% 1/8W 0805: Res Thick Film 0805 36.5K Ohm 1% 0.125W ±100ppm/°C Molded SMD Paper T/R; Manufacturer: Stackpole Electronics; Manufacturer Part Number: RMCF0805FT36K5; Manufacturer Package Identifier: 0805 (2012 metric); Max Power Dissipation: 125mW; Resistance: 36.5kΩ; Voltage Rating: 150V; LIB MADE BY: MR HOANG
U2 U3 = IC REG BUCK ADJ 3A SOT563_1: 4.2-V to 17-V input, 3-A synchronous buck converter in SOT563 6-SOT-5X3 -40 to 125; Manufacturer: Texas Instruments; Manufacturer Lifecycle Status: ACTIVE; LIB MADE BY: MR HOANG
U4 = IC REG BUCK ADJ 3A SOT23: 4.5-V to 24-V input, 3-A output synchronous buck converter 6-SOT-23-THIN -40 to 125; Manufacturer: Texas Instruments; Manufacturer Lifecycle Status: ACTIVE; LIB MADE BY: MR HOANG

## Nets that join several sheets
GND: MAIN (33 pins), POWER (31 pins)
Net3V3_1: MAIN (12 pins), POWER (6 pins)
Net4V5_1: MAIN (18 pins), POWER (7 pins)
NetC14_2: MAIN (8 pins), POWER (6 pins)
